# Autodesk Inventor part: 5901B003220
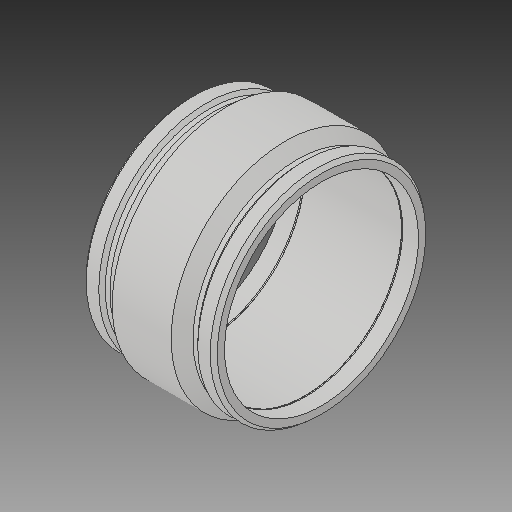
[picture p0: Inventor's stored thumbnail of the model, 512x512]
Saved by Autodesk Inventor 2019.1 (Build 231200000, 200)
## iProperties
Created: 2017-06
Part Number: 5901B003220
Material: Generic
Description: PLASSON IPS COUPLER 22''
Document SubType Name: Modeling
Designer: KIM
Mass: 8622.19 g
Surface Area: 6772.47 cm^2
Volume: 8622.19 cm^3
Density: 1 g/cm^3
Appearance: Default
Author: KIM
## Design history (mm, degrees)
derived "5901B.ipt"
feature "Solid1::5901B.ipt"
tag "TaggingFeature1"
body "Solid1"
other parameters: "d0" = 375.92, "d1" = 556.3, "d2" = 655.828, "d3" = 187.96, "d4" = 93.98, "d5" = 590.2452, "d6" = 445.04, "d7" = 556.3, "d8" = 168 deg, "d10" = 75.184, "d11" = 25.06133, "d13" = 375.92, "d14" = 17.6296, "d18" = 556.3, "d19" = 3.52592, "d20" = 168 deg, "d22" = 616.47832, "d23" = 655.828, "d24" = 597.98397, "d25" = 135 deg, "d26" = 169.164, "d27" = 135 deg, "d29" = 317.5, "d30" = 15, "d31" = 131.572, "d34" = 5 deg, "d35" = 15, "d39" = 5 deg, "d41" = 4, "d42" = 14, "d43" = 0, "d45" = 4, "d46" = 14, "d47" = 0, "d48" = 3, "d49" = 0, "d50" = 3, "d51" = 0, "d52" = 54.5084, "d53" = 13.6271, "d55" = 187.96, "d_" = 556.3, "L_" = 375.92, "L_1" = 187.96, "D_" = 655.828, "A_" = 317.5, "d_2" = 12, "B_" = 317.5
